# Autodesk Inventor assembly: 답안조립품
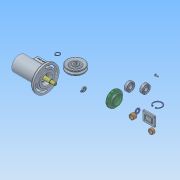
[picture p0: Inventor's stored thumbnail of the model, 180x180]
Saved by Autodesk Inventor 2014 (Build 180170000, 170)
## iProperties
Created: 2017-05
Part Number: 답안조립품
Document SubType Name: Assembly
Designer: NET
Author: NET
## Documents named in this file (16)
- C:\Users\NET\Desktop\470507V1006\답안조립품.iam
- C:\Users\NET\Desktop\470507V1006\본체.ipt
- C:\Users\NET\Desktop\470507V1006\V-벨트풀리.ipt
- C:\Users\NET\Desktop\470507V1006\너트 M10.ipt
- C:\Users\NET\Desktop\470507V1006\멈춤링 15 x 1.ipt
- C:\Users\NET\Desktop\470507V1006\멈춤링 35x1.6.ipt
- C:\Users\NET\Desktop\470507V1006\베어링 15 x 35 x 11.ipt
- C:\Users\NET\Desktop\470507V1006\볼트 M4 x 10.ipt
- C:\Users\NET\Desktop\470507V1006\축.ipt
- C:\Users\NET\Desktop\470507V1006\탑 커버.ipt
- C:\Users\NET\Desktop\470507V1006\부시2.ipt
- C:\Users\NET\Desktop\470507V1006\부시1.ipt
- C:\Users\NET\Desktop\470507V1006\와셔 10x21.ipt
- C:\Users\NET\Desktop\470507V1006\사이드 커버.ipt
- 사이드 커버.ipt
- C:\Users\NET\Desktop\470507V1006\키 4 x 4 x 18.ipt
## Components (2 placed, 2 different names)
1. V-벨트풀리:1
2. ISO 4017 M4 x 10:1
